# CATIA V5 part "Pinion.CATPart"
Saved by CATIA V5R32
Part number: Part3
Bounding box of the stored display mesh (mm): x -15 to 0, y -25 to 25, z 10.489 to 60.125
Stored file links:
  D:\PROJECTS\Project 2022\CATIA V5 6R 2022\Resources\Part Files\c16_catia_v5_6r2022_prt\Rack Joint-(Fig16-57)\Pinion.CATPart
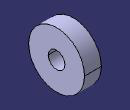
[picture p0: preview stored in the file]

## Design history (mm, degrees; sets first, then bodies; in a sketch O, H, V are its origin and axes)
Body1 (main body)
  Sketch1 on yz-plane, origin (0, 0, 0), H (0, 1, 0), V (0, 0, 1)
    reference intersected line E1 through (0, 0) direction (-1, 0) from xy-plane
    reference intersected line E3 through (0, 0) direction (0, 1) from zx-plane
    reference intersected line E4 through (0, 0) direction (-1, 0) from xy-plane
    reference intersected line E6 through (0, 0) direction (0, 1) from zx-plane
    reference intersected line E7 through (0, 0) direction (-1, 0) from xy-plane
    reference intersected line E9 through (0, 0) direction (0, 1) from zx-plane
    circle A1 centre (0, 35.3069) radius 25
    point P1 (0, 35.3069)
    circle A2 centre (0, 35.3069) radius 7.5
    radius A1 = 25
    radius A2 = 7.5
    vertical: E3 V, E6 V, E9 V
    horizontal: E1 H, E4 H, E7 H
    coincidence: P1 V
  Pad1: profile Sketch1, direction (1, 0, 0), length -15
